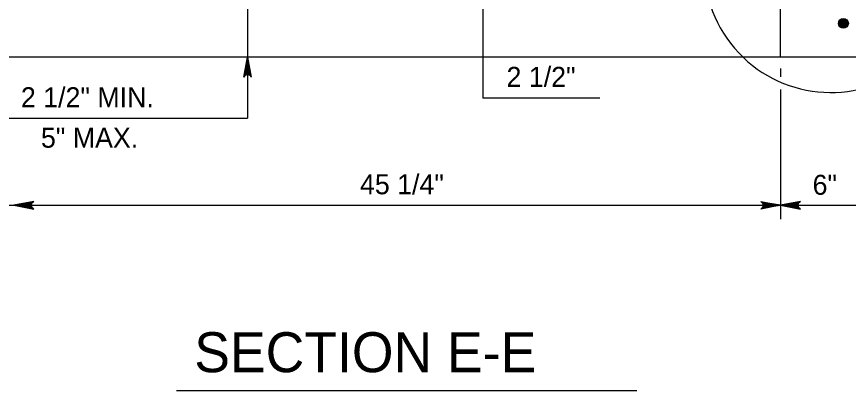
# Model space of a CAD drawing. Extents: x 2087776 to 2104538, y 970919 to 982612.
# Drawn here: x 2096408.5 to 2096817.6, y 973431.3 to 973615.4 of the extents above; entities that cross this region are included whole.
import ezdxf

# ---------------------------------------------------------------- set-up
doc = ezdxf.new("R2010")
doc.units = 0
doc.layers.add('1', color=7, linetype='Continuous')

msp = doc.modelspace()

# ---------------------------------------------------------------- linework, layer by layer
at = {"layer": '1'}
for p, q in [((2096522.11, 973749.63), (2096522.11, 973565.49)), ((2096637.87, 973700.66), (2096637.87, 973575.25)), ((2096784.27, 973595.44), (2096784.27, 973657.96)), ((2096834.27, 973595.44), (2096357.19, 973595.44)), ((2096784.27, 973589.89), (2096784.27, 973585.84)), ((2096784.27, 973579.53), (2096784.27, 973515.7)), ((2096695.43, 973575.25), (2096637.87, 973575.25)), ((2096384.89, 973565.49), (2096522.11, 973565.49)), ((2096357.19, 973522.49), (2096834.27, 973522.49)), ((2096487.2, 973431.35), (2096713.61, 973431.35))]:
    msp.add_line(p, q, dxfattribs=at)
for points in [[(2096522.11, 973595.44), (2096523.94, 973585.66), (2096523.68, 973586.03), (2096523.42, 973586.41), (2096523.09, 973586.6), (2096522.77, 973586.8), (2096522.44, 973586.85), (2096522.11, 973586.91), (2096521.78, 973586.85), (2096521.45, 973586.8), (2096521.13, 973586.6), (2096520.8, 973586.41), (2096520.54, 973586.03), (2096520.28, 973585.66), (2096522.11, 973595.44), (2096520.54, 973586.03), (2096520.8, 973586.41), (2096522.11, 973595.44), (2096521.13, 973586.6), (2096521.45, 973586.8), (2096522.11, 973595.44), (2096521.78, 973586.85), (2096522.11, 973586.91), (2096522.11, 973595.44), (2096522.44, 973586.85), (2096522.77, 973586.8), (2096522.11, 973595.44), (2096523.09, 973586.6), (2096523.42, 973586.41), (2096522.11, 973595.44), (2096523.68, 973586.03)], [(2096407.19, 973522.49), (2096416.98, 973520.65), (2096416.6, 973520.92), (2096416.23, 973521.18), (2096416.03, 973521.5), (2096415.84, 973521.83), (2096415.78, 973522.16), (2096415.72, 973522.49), (2096415.78, 973522.82), (2096415.84, 973523.15), (2096416.03, 973523.47), (2096416.23, 973523.8), (2096416.6, 973524.06), (2096416.98, 973524.32), (2096407.19, 973522.49), (2096416.6, 973524.06), (2096416.23, 973523.8), (2096407.19, 973522.49), (2096416.03, 973523.47), (2096415.84, 973523.15), (2096407.19, 973522.49), (2096415.78, 973522.82), (2096415.72, 973522.49), (2096407.19, 973522.49), (2096415.78, 973522.16), (2096415.84, 973521.83), (2096407.19, 973522.49), (2096416.03, 973521.5), (2096416.23, 973521.18), (2096407.19, 973522.49), (2096416.6, 973520.92)], [(2096784.27, 973522.49), (2096774.48, 973520.65), (2096774.86, 973520.92), (2096775.24, 973521.18), (2096775.43, 973521.5), (2096775.63, 973521.83), (2096775.68, 973522.16), (2096775.74, 973522.49), (2096775.68, 973522.82), (2096775.63, 973523.15), (2096775.43, 973523.47), (2096775.24, 973523.8), (2096774.86, 973524.06), (2096774.48, 973524.32), (2096784.27, 973522.49), (2096774.86, 973524.06), (2096775.24, 973523.8), (2096784.27, 973522.49), (2096775.43, 973523.47), (2096775.63, 973523.15), (2096784.27, 973522.49), (2096775.68, 973522.82), (2096775.74, 973522.49), (2096784.27, 973522.49), (2096775.68, 973522.16), (2096775.63, 973521.83), (2096784.27, 973522.49), (2096775.43, 973521.5), (2096775.24, 973521.18), (2096784.27, 973522.49), (2096774.86, 973520.92)], [(2096784.27, 973522.49), (2096794.05, 973520.65), (2096793.68, 973520.92), (2096793.3, 973521.18), (2096793.11, 973521.5), (2096792.91, 973521.83), (2096792.86, 973522.16), (2096792.8, 973522.49), (2096792.86, 973522.82), (2096792.91, 973523.15), (2096793.11, 973523.47), (2096793.3, 973523.8), (2096793.68, 973524.06), (2096794.05, 973524.32), (2096784.27, 973522.49), (2096793.68, 973524.06), (2096793.3, 973523.8), (2096784.27, 973522.49), (2096793.11, 973523.47), (2096792.91, 973523.15), (2096784.27, 973522.49), (2096792.86, 973522.82), (2096792.8, 973522.49), (2096784.27, 973522.49), (2096792.86, 973522.16), (2096792.91, 973521.83), (2096784.27, 973522.49), (2096793.11, 973521.5), (2096793.3, 973521.18), (2096784.27, 973522.49), (2096793.68, 973520.92)]]:
    msp.add_lwpolyline(points, dxfattribs=at)
for radius in [2.45, 2.27, 2.1, 1.93, 1.75, 1.58, 1.4, 1.23, 1.06, 0.883, 0.709, 0.535, 0.361, 0.188]:
    msp.add_circle((2096815.14, 973612.11), radius, dxfattribs=at)
msp.add_arc((2096808.93, 973640.33), 62.27, 45.8156, 35.2038, dxfattribs=at)

# ---------------------------------------------------------------- texts
for s, p in [('2 1/2"', (2096649.48, 973580.82)), ('6"', (2096800, 973527.69))]:
    msp.add_text(s, height=9.843, rotation=360, dxfattribs=at).set_placement(p)
for s, height, p in [('2 1/2" MIN.', 9.8425, (2096410.66, 973570.79)), ('5" MAX.', 9.843, (2096420.5, 973550.87)), ('45 1/4"', 9.843, (2096577.4, 973527.93)), ('SECTION E-E', 19.685, (2096495.9, 973440.3))]:
    msp.add_text(s, height=height, dxfattribs=at).set_placement(p)

doc.saveas('drawing.dxf')
